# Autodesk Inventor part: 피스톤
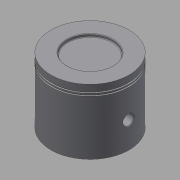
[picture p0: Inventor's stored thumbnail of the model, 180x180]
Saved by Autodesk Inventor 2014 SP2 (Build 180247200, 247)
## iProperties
Created: 2016-11
Part Number: 피스톤
Material: 강철, 탄소
Document SubType Name: Modeling
Designer: mduedu
Density: 7.87 g/cm^3
Mass: 410.154 g
Surface Area: 237.492 cm^2
Volume: 52.1161 cm^3
Appearance: 기본값
Author: mduedu
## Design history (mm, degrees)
sketch "스케치1"
  geometry: C1 r 30 at (0, 0); 1 further point
  constraints: 1 centre point, 1 coincident
  dimensions: "d0" = 60 diameter of C1
extrude "돌출1" new body sketch "스케치1" distance "d1" = 50; taper "d2" = 0 deg
sketch "스케치2"
  geometry: C1 r 28 at (0, 0); 1 further point
  constraints: 1 centre point, 1 coincident
  dimensions: "d3" = 56 diameter of C1
extrude "돌출2" cut sketch "스케치2" distance "d4" = 45; taper "d5" = 0 deg
sketch "스케치3"
  geometry: L1 (30, 0)-(30, 50) reference; L2 (30, 45)-(29, 45); L3 (29, 45)-(29, 44); L4 (29, 44)-(30, 44); L5 (30, 44)-(30, 45); L6 (30, 43)-(29, 43); L7 (29, 43)-(29, 42); L8 (29, 42)-(30, 42); L9 (30, 42)-(30, 43); L10 (30, 50)-(-30, 50) reference; L11 (0, 50)-(0, 0)
  constraints: 18 end point, 4 parallel, 3 equal length, 3 perpendicular, 2 horizontal, 2 point on line, 1 midpoint
  dimensions: "d6" = 1 distance of L2.start L2.end; "d8" = 5 distance between parallel lines of L10 L2; "d9" = 1 distance between parallel lines of L6 L4
revolve "회전1" sketch "스케치3" stored, may be unused: angle "d10" = 90 deg
node "작업 평면1"
sketch "스케치4"
  geometry: L1 (0, -22.978)-(45, -22.978) reference; L2 (45, -22.978)-(45, 22.978) reference; L3 (45, 22.978)-(0, 22.978) reference; L4 (0, 22.978)-(0, 25.377) reference; L5 (0, 25.377)-(42, 25.377) reference; L6 (42, 25.377)-(42, 24.187) reference; L7 (42, 24.187)-(43, 24.187) reference; L8 (43, 24.187)-(43, 25.377) reference; L9 (43, 25.377)-(44, 25.377) reference; L10 (44, 25.377)-(44, 24.187) reference; L11 (44, 24.187)-(45, 24.187) reference; L12 (45, 24.187)-(45, 25.377) reference; L13 (45, 25.377)-(50, 25.377) reference; L14 (50, 25.377)-(50, -25.377) reference; L15 (50, -25.377)-(45, -25.377) reference; L16 (45, -25.377)-(45, -24.187) reference; L17 (45, -24.187)-(44, -24.187) reference; L18 (44, -24.187)-(44, -25.377) reference; L19 (44, -25.377)-(43, -25.377) reference; L20 (43, -25.377)-(43, -24.187) reference; L21 (43, -24.187)-(42, -24.187) reference; L22 (42, -24.187)-(42, -25.377) reference; L23 (42, -25.377)-(0, -25.377) reference; L24 (0, -25.377)-(0, -22.978) reference; L25 (12.5, 22.978)-(45, 22.978); L26 (45, 22.978)-(45, -22.978); L27 (45, -22.978)-(12.5, -22.978); L28 (12.5, -22.978)-(12.5, 22.978); C1 r 7.5 at (20, 0); C2 r 4 at (20, 0); 1 further point
  constraints: 8 end point, 2 centre point, 2 parallel, 1 coincident, 1 horizontal, 1 horizontal alignment, 1 perpendicular, 1 point on line, 1 tangent
  dimensions: "d12" = 15 diameter of C1; "d13" = 8 diameter of C2; "d14" = 20 distance of point (0, 0) C1.centre
  node "절단 모서리 투영1"
extrude "돌출3" join sketch "스케치4" stored distance "d15" = 11.75; taper "d16" = 0 deg
extrude "돌출4" cut sketch "스케치4" stored distance "d17" = 72; taper "d18" = 0 deg
fillet "모깎기2" dims "d20" = 3
chamfer "모따기1" distance "d21" = 0.5; stored, may be unused: second distance "d22" = 2, angle "d23" = 45 deg
chamfer "모따기2" distance "d24" = 0.5; stored, may be unused: second distance "d25" = 2, angle "d26" = 45 deg
sketch "스케치5"
  geometry: C1 r 17.5 at (0, 0); 1 further point
  constraints: 1 centre point, 1 coincident
  dimensions: "d27" = 35 diameter of C1
extrude "돌출5" cut sketch "스케치5" distance "d28" = 2; taper "d29" = 0 deg
fillet "모깎기3" dims "d30" = 0.5
node "솔리드1"
mirror "대칭1"
other parameters: "d11" = -16
